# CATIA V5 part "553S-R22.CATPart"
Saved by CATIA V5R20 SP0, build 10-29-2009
Part number: 553S-R22
Definition: NONE
Nomenclature: 553S-R22
Source: Unknown
Description: 553S-R22
Bounding box of the stored display mesh (mm): x -12.5 to 12.5, y -13.31 to 13.491, z -0.6 to 0.6
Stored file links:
  C:\Users\Utente\Desktop\IO LAVORO\3D X SITO CF\X SITO\PLASTICA\553S\553S-R22.CATPart
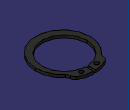
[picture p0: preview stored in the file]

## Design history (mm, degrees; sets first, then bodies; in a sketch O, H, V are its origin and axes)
Body1 "553S-R22" (main body)
  Solid1: solid without history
